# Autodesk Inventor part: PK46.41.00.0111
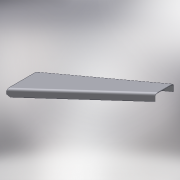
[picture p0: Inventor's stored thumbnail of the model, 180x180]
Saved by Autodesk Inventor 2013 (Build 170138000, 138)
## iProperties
Created: 2005-07
Part Number: PK46.41.00.0111
Material: Steel, Mild
Document SubType Name: Modeling
Designer: tedescj
Manufacturer: Standard
Standards Organization: Custom
Mass: 1058.63 g
Surface Area: 929.402 cm^2
Volume: 134.686 cm^3
Density: 7.86 g/cm^3
Author: PVitaliy
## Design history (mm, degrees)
derived "PK46.41.00.011.ipt"
feature "Solid1::PK46.41.00.011.ipt" dims "d0" = 10
tag "TaggingFeature1"
body "Solid1"
